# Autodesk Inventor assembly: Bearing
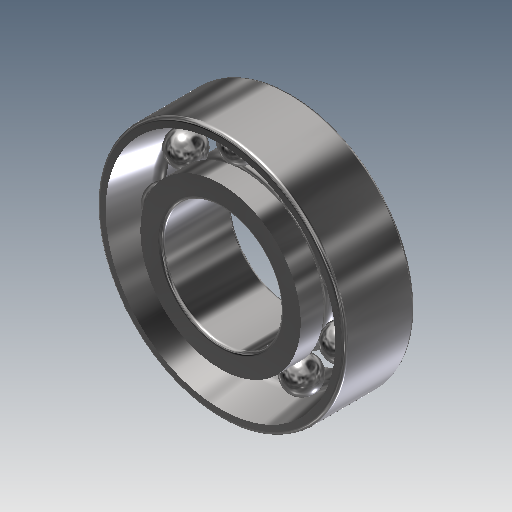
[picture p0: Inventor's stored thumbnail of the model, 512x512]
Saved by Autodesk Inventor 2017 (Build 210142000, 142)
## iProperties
ClientObjectVersion: 1
Created: 2019-02
Part Number: Bearing
Document SubType Name: Assembly
Designer: user
Author: user
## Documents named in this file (2)
- C:\Users\user\Desktop\Ensamble reductor de velocidad\Ensamble\Design Accelerator\Bearing4.iam
- C:\Users\user\Documents\Inventor\Content Center Files\R2017\en-US\BS 292 (II)\BS 292_ Part 1 - 7004 - 20 x 42 x 12.ipt
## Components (1 placed, 1 different names)
1. BS 292: Part 1 (II) - Metric 7004 - 20 x 42 x 12:1
